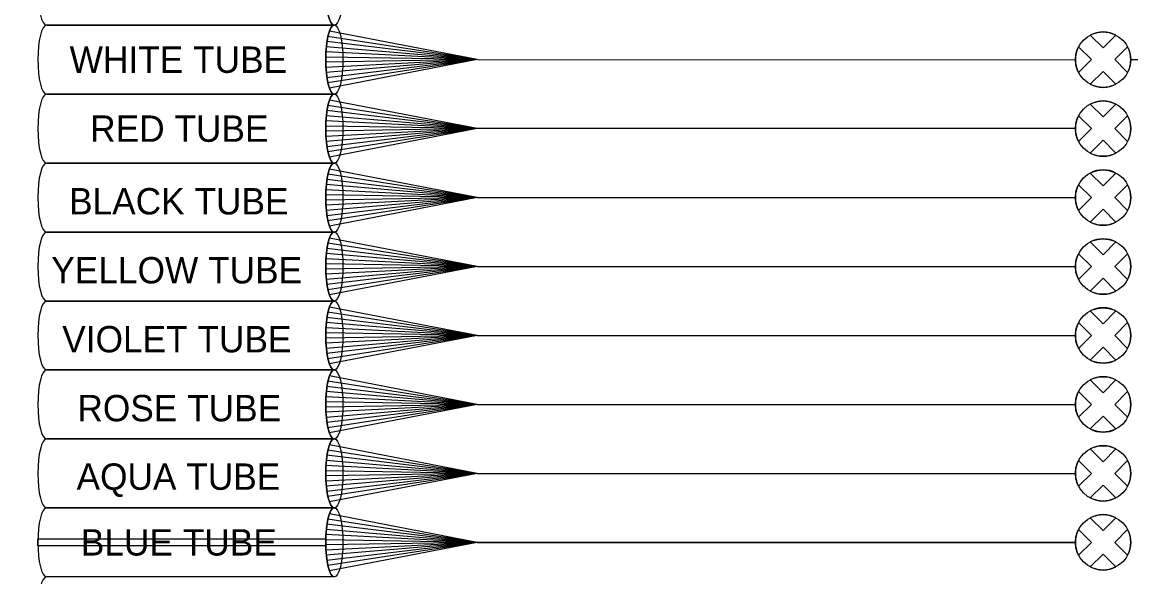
# Model space of a CAD drawing. Extents: x 1805893 to 1833564, y 708898 to 716199.
# Drawn here: x 1831642.7 to 1831739.1, y 715918.7 to 715967 of the extents above; entities that cross this region are included whole.
import ezdxf

# ---------------------------------------------------------------- set-up
doc = ezdxf.new("R2010")
doc.units = 0
doc.layers.add('SH_Data', color=7, linetype='Continuous')

msp = doc.modelspace()

# ---------------------------------------------------------------- linework, layer by layer
at = {"layer": 'SH_Data'}
for p, q in [((1831669.823, 715966.733), (1831644.773, 715966.733)), ((1831644.773, 715966.733), (1831669.823, 715966.733)), ((1831682.244, 715963.733), (1831669.4, 715966.208)), ((1831682.244, 715963.733), (1831669.185, 715965.308)), ((1831682.244, 715963.733), (1831669.27, 715965.758)), ((1831736.727, 715964.75), (1831735.608, 715965.869)), ((1831735.608, 715965.869), (1831736.727, 715964.75)), ((1831736.727, 715964.75), (1831737.846, 715965.869)), ((1831736.727, 715964.75), (1831737.846, 715965.869)), ((1831682.244, 715963.733), (1831669.093, 715964.408)), ((1831682.244, 715963.733), (1831669.128, 715964.858)), ((1831735.71, 715963.733), (1831734.591, 715964.852)), ((1831735.71, 715963.733), (1831734.591, 715964.852)), ((1831737.744, 715963.733), (1831738.863, 715964.852)), ((1831738.863, 715964.852), (1831737.744, 715963.733)), ((1831682.244, 715963.733), (1831669.076, 715963.958)), ((1831682.244, 715963.733), (1831669.076, 715963.508)), ((1831682.244, 715963.733), (1831669.093, 715963.058)), ((1831682.244, 715963.733), (1831669.128, 715962.608)), ((1831682.244, 715963.733), (1831669.185, 715962.158)), ((1831682.244, 715963.733), (1831669.27, 715961.708)), ((1831682.244, 715963.733), (1831669.4, 715961.258)), ((1831682.244, 715963.733), (1831734.316, 715963.711)), ((1831734.591, 715962.614), (1831735.71, 715963.733)), ((1831734.591, 715962.614), (1831735.71, 715963.733)), ((1831738.863, 715962.614), (1831737.744, 715963.733)), ((1831737.744, 715963.733), (1831738.863, 715962.614)), ((1831791.211, 715963.733), (1831739.139, 715963.711)), ((1831735.608, 715961.597), (1831736.727, 715962.716)), ((1831736.727, 715962.716), (1831735.608, 715961.597)), ((1831737.846, 715961.597), (1831736.727, 715962.716)), ((1831737.846, 715961.597), (1831736.727, 715962.716)), ((1831669.823, 715960.733), (1831644.773, 715960.733)), ((1831644.773, 715960.733), (1831669.823, 715960.733)), ((1831682.244, 715957.733), (1831669.27, 715959.758)), ((1831682.244, 715957.733), (1831669.4, 715960.208)), ((1831736.727, 715958.75), (1831735.608, 715959.869)), ((1831735.608, 715959.869), (1831736.727, 715958.75)), ((1831736.727, 715958.75), (1831737.846, 715959.869)), ((1831736.727, 715958.75), (1831737.846, 715959.869)), ((1831682.244, 715957.733), (1831669.128, 715958.858)), ((1831682.244, 715957.733), (1831669.185, 715959.308)), ((1831735.71, 715957.733), (1831734.591, 715958.852)), ((1831735.71, 715957.733), (1831734.591, 715958.852)), ((1831737.744, 715957.733), (1831738.863, 715958.852)), ((1831738.863, 715958.852), (1831737.744, 715957.733)), ((1831682.244, 715957.733), (1831669.076, 715957.958)), ((1831682.244, 715957.733), (1831669.076, 715957.508)), ((1831682.244, 715957.733), (1831669.093, 715958.408)), ((1831682.244, 715957.733), (1831669.093, 715957.058)), ((1831682.244, 715957.733), (1831669.128, 715956.608)), ((1831682.244, 715957.733), (1831669.185, 715956.158)), ((1831682.244, 715957.733), (1831669.27, 715955.708)), ((1831682.244, 715957.733), (1831669.4, 715955.258)), ((1831734.316, 715957.733), (1831682.244, 715957.733)), ((1831734.591, 715956.614), (1831735.71, 715957.733)), ((1831734.591, 715956.614), (1831735.71, 715957.733)), ((1831738.863, 715956.614), (1831737.744, 715957.733)), ((1831737.744, 715957.733), (1831738.863, 715956.614)), ((1831735.608, 715955.597), (1831736.727, 715956.716)), ((1831736.727, 715956.716), (1831735.608, 715955.597)), ((1831737.846, 715955.597), (1831736.727, 715956.716)), ((1831737.846, 715955.597), (1831736.727, 715956.716)), ((1831669.823, 715954.733), (1831644.773, 715954.733)), ((1831644.773, 715954.733), (1831669.823, 715954.733)), ((1831682.244, 715951.733), (1831669.27, 715953.758)), ((1831682.244, 715951.733), (1831669.4, 715954.208)), ((1831736.727, 715952.75), (1831735.608, 715953.869)), ((1831735.608, 715953.869), (1831736.727, 715952.75)), ((1831736.727, 715952.75), (1831737.846, 715953.869)), ((1831736.727, 715952.75), (1831737.846, 715953.869)), ((1831682.244, 715951.733), (1831669.128, 715952.858)), ((1831682.244, 715951.733), (1831669.185, 715953.308)), ((1831735.71, 715951.733), (1831734.591, 715952.852)), ((1831735.71, 715951.733), (1831734.591, 715952.852)), ((1831737.744, 715951.733), (1831738.863, 715952.852)), ((1831738.863, 715952.852), (1831737.744, 715951.733)), ((1831682.244, 715951.733), (1831669.076, 715951.958)), ((1831682.244, 715951.733), (1831669.076, 715951.508)), ((1831682.244, 715951.733), (1831669.093, 715952.408)), ((1831682.244, 715951.733), (1831669.093, 715951.058)), ((1831682.244, 715951.733), (1831669.128, 715950.608)), ((1831682.244, 715951.733), (1831669.185, 715950.158)), ((1831682.244, 715951.733), (1831669.27, 715949.708)), ((1831682.244, 715951.733), (1831669.4, 715949.258)), ((1831682.244, 715951.733), (1831734.316, 715951.733)), ((1831734.591, 715950.614), (1831735.71, 715951.733)), ((1831734.591, 715950.614), (1831735.71, 715951.733)), ((1831738.863, 715950.614), (1831737.744, 715951.733)), ((1831737.744, 715951.733), (1831738.863, 715950.614)), ((1831735.608, 715949.597), (1831736.727, 715950.716)), ((1831736.727, 715950.716), (1831735.608, 715949.597)), ((1831737.846, 715949.597), (1831736.727, 715950.716)), ((1831737.846, 715949.597), (1831736.727, 715950.716)), ((1831644.773, 715948.733), (1831669.823, 715948.733)), ((1831669.823, 715948.733), (1831644.773, 715948.733)), ((1831682.244, 715945.733), (1831669.4, 715948.208)), ((1831736.727, 715946.75), (1831735.608, 715947.869)), ((1831735.608, 715947.869), (1831736.727, 715946.75)), ((1831736.727, 715946.75), (1831737.846, 715947.869)), ((1831736.727, 715946.75), (1831737.846, 715947.869)), ((1831682.244, 715945.733), (1831669.128, 715946.858)), ((1831682.244, 715945.733), (1831669.185, 715947.308)), ((1831682.244, 715945.733), (1831669.27, 715947.758)), ((1831735.71, 715945.733), (1831734.591, 715946.852)), ((1831735.71, 715945.733), (1831734.591, 715946.852)), ((1831737.744, 715945.733), (1831738.863, 715946.852)), ((1831738.863, 715946.852), (1831737.744, 715945.733)), ((1831682.244, 715945.733), (1831669.076, 715945.958)), ((1831682.244, 715945.733), (1831669.093, 715946.408)), ((1831682.244, 715945.733), (1831669.076, 715945.508)), ((1831682.244, 715945.733), (1831669.093, 715945.058)), ((1831682.244, 715945.733), (1831669.128, 715944.608)), ((1831682.244, 715945.733), (1831669.185, 715944.158)), ((1831682.244, 715945.733), (1831669.27, 715943.708)), ((1831682.244, 715945.733), (1831669.4, 715943.258)), ((1831682.244, 715945.733), (1831734.316, 715945.733)), ((1831734.591, 715944.614), (1831735.71, 715945.733)), ((1831734.591, 715944.614), (1831735.71, 715945.733)), ((1831738.863, 715944.614), (1831737.744, 715945.733)), ((1831737.744, 715945.733), (1831738.863, 715944.614)), ((1831735.608, 715943.597), (1831736.727, 715944.716)), ((1831736.727, 715944.716), (1831735.608, 715943.597)), ((1831737.846, 715943.597), (1831736.727, 715944.716)), ((1831737.846, 715943.597), (1831736.727, 715944.716)), ((1831669.823, 715942.733), (1831644.773, 715942.733)), ((1831644.773, 715942.733), (1831669.823, 715942.733)), ((1831644.773, 715942.733), (1831669.823, 715942.733)), ((1831682.244, 715939.733), (1831669.4, 715942.208)), ((1831682.244, 715939.733), (1831669.185, 715941.308)), ((1831682.244, 715939.733), (1831669.27, 715941.758)), ((1831736.727, 715940.75), (1831735.608, 715941.869)), ((1831735.608, 715941.869), (1831736.727, 715940.75)), ((1831736.727, 715940.75), (1831737.846, 715941.869)), ((1831736.727, 715940.75), (1831737.846, 715941.869)), ((1831682.244, 715939.733), (1831669.093, 715940.408)), ((1831682.244, 715939.733), (1831669.128, 715940.858)), ((1831735.71, 715939.733), (1831734.591, 715940.852)), ((1831735.71, 715939.733), (1831734.591, 715940.852)), ((1831737.744, 715939.733), (1831738.863, 715940.852)), ((1831738.863, 715940.852), (1831737.744, 715939.733)), ((1831682.244, 715939.733), (1831669.076, 715939.958)), ((1831682.244, 715939.733), (1831669.076, 715939.508)), ((1831682.244, 715939.733), (1831669.093, 715939.058)), ((1831682.244, 715939.733), (1831669.128, 715938.608)), ((1831682.244, 715939.733), (1831669.185, 715938.158)), ((1831682.244, 715939.733), (1831669.27, 715937.708)), ((1831682.244, 715939.733), (1831669.4, 715937.258)), ((1831682.244, 715939.733), (1831734.316, 715939.733)), ((1831734.591, 715938.614), (1831735.71, 715939.733)), ((1831734.591, 715938.614), (1831735.71, 715939.733)), ((1831738.863, 715938.614), (1831737.744, 715939.733)), ((1831737.744, 715939.733), (1831738.863, 715938.614)), ((1831735.608, 715937.597), (1831736.727, 715938.716)), ((1831736.727, 715938.716), (1831735.608, 715937.597)), ((1831737.846, 715937.597), (1831736.727, 715938.716)), ((1831737.846, 715937.597), (1831736.727, 715938.716)), ((1831669.823, 715936.733), (1831644.773, 715936.733)), ((1831644.773, 715936.733), (1831669.823, 715936.733)), ((1831682.244, 715933.733), (1831669.185, 715935.308)), ((1831682.244, 715933.733), (1831669.27, 715935.758)), ((1831682.244, 715933.733), (1831669.4, 715936.208)), ((1831736.727, 715934.75), (1831735.608, 715935.869)), ((1831735.608, 715935.869), (1831736.727, 715934.75)), ((1831736.727, 715934.75), (1831737.846, 715935.869)), ((1831736.727, 715934.75), (1831737.846, 715935.869)), ((1831682.244, 715933.733), (1831669.093, 715934.408)), ((1831682.244, 715933.733), (1831669.128, 715934.858)), ((1831735.71, 715933.733), (1831734.591, 715934.852)), ((1831735.71, 715933.733), (1831734.591, 715934.852)), ((1831737.744, 715933.733), (1831738.863, 715934.852)), ((1831738.863, 715934.852), (1831737.744, 715933.733)), ((1831682.244, 715933.733), (1831669.076, 715933.958)), ((1831682.244, 715933.733), (1831669.076, 715933.508)), ((1831682.244, 715933.733), (1831669.093, 715933.058)), ((1831682.244, 715933.733), (1831669.128, 715932.608)), ((1831682.244, 715933.733), (1831669.185, 715932.158)), ((1831682.244, 715933.733), (1831669.27, 715931.708)), ((1831682.244, 715933.733), (1831669.4, 715931.258)), ((1831682.244, 715933.733), (1831734.316, 715933.733)), ((1831734.591, 715932.614), (1831735.71, 715933.733)), ((1831734.591, 715932.614), (1831735.71, 715933.733)), ((1831738.863, 715932.614), (1831737.744, 715933.733)), ((1831737.744, 715933.733), (1831738.863, 715932.614)), ((1831735.608, 715931.597), (1831736.727, 715932.716)), ((1831736.727, 715932.716), (1831735.608, 715931.597)), ((1831737.846, 715931.597), (1831736.727, 715932.716)), ((1831737.846, 715931.597), (1831736.727, 715932.716)), ((1831669.823, 715930.733), (1831644.773, 715930.733)), ((1831644.773, 715930.733), (1831669.823, 715930.733)), ((1831682.244, 715927.733), (1831669.27, 715929.758)), ((1831682.244, 715927.733), (1831669.4, 715930.208)), ((1831736.727, 715928.75), (1831735.608, 715929.869)), ((1831735.608, 715929.869), (1831736.727, 715928.75)), ((1831736.727, 715928.75), (1831737.846, 715929.869)), ((1831736.727, 715928.75), (1831737.846, 715929.869)), ((1831682.244, 715927.733), (1831669.128, 715928.858)), ((1831682.244, 715927.733), (1831669.185, 715929.308)), ((1831735.71, 715927.733), (1831734.591, 715928.852)), ((1831735.71, 715927.733), (1831734.591, 715928.852)), ((1831737.744, 715927.733), (1831738.863, 715928.852)), ((1831738.863, 715928.852), (1831737.744, 715927.733)), ((1831682.244, 715927.733), (1831669.076, 715927.958)), ((1831682.244, 715927.733), (1831669.076, 715927.508)), ((1831682.244, 715927.733), (1831669.093, 715928.408)), ((1831682.244, 715927.733), (1831669.093, 715927.058)), ((1831682.244, 715927.733), (1831669.128, 715926.608)), ((1831682.244, 715927.733), (1831669.185, 715926.158)), ((1831682.244, 715927.733), (1831669.27, 715925.708)), ((1831682.244, 715927.733), (1831669.4, 715925.258)), ((1831682.244, 715927.733), (1831734.316, 715927.711)), ((1831734.591, 715926.614), (1831735.71, 715927.733)), ((1831734.591, 715926.614), (1831735.71, 715927.733)), ((1831738.863, 715926.614), (1831737.744, 715927.733)), ((1831737.744, 715927.733), (1831738.863, 715926.614)), ((1831735.608, 715925.597), (1831736.727, 715926.716)), ((1831736.727, 715926.716), (1831735.608, 715925.597)), ((1831737.846, 715925.597), (1831736.727, 715926.716)), ((1831737.846, 715925.597), (1831736.727, 715926.716)), ((1831669.823, 715924.733), (1831644.773, 715924.733)), ((1831644.773, 715924.733), (1831669.823, 715924.733)), ((1831682.244, 715921.733), (1831669.27, 715923.758)), ((1831682.244, 715921.733), (1831669.4, 715924.208)), ((1831736.727, 715922.75), (1831735.608, 715923.869)), ((1831735.608, 715923.869), (1831736.727, 715922.75)), ((1831736.727, 715922.75), (1831737.846, 715923.869)), ((1831736.727, 715922.75), (1831737.846, 715923.869)), ((1831682.244, 715921.733), (1831669.128, 715922.858)), ((1831682.244, 715921.733), (1831669.185, 715923.308)), ((1831735.71, 715921.733), (1831734.591, 715922.852)), ((1831735.71, 715921.733), (1831734.591, 715922.852)), ((1831737.744, 715921.733), (1831738.863, 715922.852)), ((1831738.863, 715922.852), (1831737.744, 715921.733)), ((1831682.244, 715921.733), (1831669.076, 715921.958)), ((1831682.244, 715921.733), (1831669.093, 715922.408)), ((1831682.244, 715921.733), (1831669.076, 715921.508)), ((1831682.244, 715921.733), (1831669.093, 715921.058)), ((1831682.244, 715921.733), (1831669.128, 715920.608)), ((1831682.244, 715921.733), (1831669.185, 715920.158)), ((1831682.244, 715921.733), (1831669.27, 715919.708)), ((1831682.244, 715921.733), (1831669.4, 715919.258)), ((1831682.244, 715921.733), (1831734.316, 715921.733)), ((1831734.316, 715921.733), (1831682.244, 715921.733)), ((1831734.591, 715920.614), (1831735.71, 715921.733)), ((1831734.591, 715920.614), (1831735.71, 715921.733)), ((1831738.863, 715920.614), (1831737.744, 715921.733)), ((1831737.744, 715921.733), (1831738.863, 715920.614)), ((1831735.608, 715919.597), (1831736.727, 715920.716)), ((1831736.727, 715920.716), (1831735.608, 715919.597)), ((1831737.846, 715919.597), (1831736.727, 715920.716)), ((1831737.846, 715919.597), (1831736.727, 715920.716)), ((1831669.823, 715918.733), (1831644.773, 715918.733))]:
    msp.add_line(p, q, dxfattribs=at)
msp.add_lwpolyline([(1831644.027, 715922.033), (1831669.075, 715922.033), (1831669.075, 715921.433), (1831644.027, 715921.433)], close=True, dxfattribs=at)
for centre in [(1831736.727, 715963.733), (1831736.727, 715957.733), (1831736.727, 715951.733), (1831736.727, 715945.733), (1831736.727, 715939.733), (1831736.727, 715933.733), (1831736.727, 715927.733), (1831736.727, 715921.733)]:
    msp.add_circle(centre, 2.411, dxfattribs=at)
for centre, start, end in [((1831736.727, 715963.733), 62.353, 117.647), ((1831736.727, 715963.733), 152.353, 207.647), ((1831736.727, 715963.733), 332.353, 27.647), ((1831736.727, 715963.733), 242.353, 297.647), ((1831736.727, 715957.733), 62.353, 117.647), ((1831736.727, 715957.733), 152.353, 207.647), ((1831736.727, 715957.733), 332.353, 27.647), ((1831736.727, 715957.733), 242.353, 297.647), ((1831736.727, 715951.733), 62.353, 117.647), ((1831736.727, 715951.733), 152.353, 207.647), ((1831736.727, 715951.733), 332.353, 27.647), ((1831736.727, 715951.733), 242.353, 297.647), ((1831736.727, 715945.733), 62.353, 117.647), ((1831736.727, 715945.733), 152.353, 207.647), ((1831736.727, 715945.733), 332.353, 27.647), ((1831736.727, 715945.733), 242.353, 297.647), ((1831736.727, 715939.733), 62.353, 117.647), ((1831736.727, 715939.733), 152.353, 207.647), ((1831736.727, 715939.733), 332.353, 27.647), ((1831736.727, 715939.733), 242.353, 297.647), ((1831736.727, 715933.733), 62.353, 117.647), ((1831736.727, 715933.733), 152.353, 207.647), ((1831736.727, 715933.733), 332.353, 27.647), ((1831736.727, 715933.733), 242.353, 297.647), ((1831736.727, 715927.733), 62.353, 117.647), ((1831736.727, 715927.733), 152.353, 207.647), ((1831736.727, 715927.733), 332.353, 27.647), ((1831736.727, 715927.733), 242.353, 297.647), ((1831736.727, 715921.733), 62.353, 117.647), ((1831736.727, 715921.733), 152.353, 207.647), ((1831736.727, 715921.733), 332.353, 27.647), ((1831736.727, 715921.733), 242.353, 297.647)]:
    msp.add_arc(centre, 2.411, start, end, dxfattribs=at)
for centre, major_axis, ratio, start_param, end_param in [((1831644.17, 715924.733), (0, -86.094), 0.112175, 2.561295, 6.863483), ((1831644.17, 715924.733), (0, -86.094), 0.112175, 2.561295, 6.863483), ((1831644.773, 715969.733), (0, -3), 0.25, 3.141593, 6.283185), ((1831644.773, 715969.733), (0, -3), 0.25, 3.141593, 6.283185), ((1831669.823, 715969.733), (0, -3), 0.25, 3.141593, 6.283185), ((1831644.773, 715963.733), (0, -3), 0.25, 3.141593, 6.283185), ((1831644.773, 715963.733), (0, -3), 0.25, 3.141593, 6.283185), ((1831669.823, 715963.733), (0, -3), 0.25, 3.141593, 6.283185), ((1831644.773, 715957.733), (0, -3), 0.25, 3.141593, 6.283185), ((1831644.773, 715957.733), (0, -3), 0.25, 3.141593, 6.283185), ((1831669.823, 715957.733), (0, -3), 0.25, 3.141593, 6.283185), ((1831644.773, 715951.733), (0, -3), 0.25, 3.141593, 6.283185), ((1831644.773, 715951.733), (0, -3), 0.25, 3.141593, 6.283185), ((1831669.823, 715951.733), (0, -3), 0.25, 3.141593, 6.283185), ((1831644.773, 715945.733), (0, -3), 0.25, 3.141593, 6.283185), ((1831644.773, 715945.733), (0, -3), 0.25, 3.141593, 6.283185), ((1831669.823, 715945.733), (0, -3), 0.25, 3.141593, 6.283185), ((1831644.773, 715939.733), (0, -3), 0.25, 3.141593, 6.283185), ((1831644.773, 715939.733), (0, -3), 0.25, 3.141593, 6.283185), ((1831669.823, 715939.733), (0, -3), 0.25, 3.141593, 6.283185), ((1831644.773, 715933.733), (0, -3), 0.25, 3.141593, 6.283185), ((1831644.773, 715933.733), (0, -3), 0.25, 3.141593, 6.283185), ((1831669.823, 715933.733), (0, -3), 0.25, 3.141593, 6.283185), ((1831644.773, 715927.733), (0, -3), 0.25, 3.141593, 6.283185), ((1831644.773, 715927.733), (0, -3), 0.25, 3.141593, 6.283185), ((1831669.823, 715927.733), (0, -3), 0.25, 3.141593, 6.283185), ((1831644.773, 715921.733), (0, -3), 0.25, 3.141593, 6.283185), ((1831644.773, 715921.733), (0, -3), 0.25, 3.141593, 6.283185), ((1831669.823, 715921.733), (0, -3), 0.25, 3.141593, 6.283185), ((1831644.773, 715915.733), (0, -3), 0.25, 3.141593, 6.283185)]:
    msp.add_ellipse(centre, major_axis=major_axis, ratio=ratio, start_param=start_param, end_param=end_param, dxfattribs=at)
for centre in [(1831669.823, 715969.733), (1831669.823, 715963.733), (1831669.823, 715957.733), (1831669.823, 715951.733), (1831669.823, 715945.733), (1831669.823, 715939.733), (1831669.823, 715933.733), (1831669.823, 715927.733), (1831669.823, 715921.733)]:
    msp.add_ellipse(centre, major_axis=(0, -3), ratio=0.25, dxfattribs=at)

# ---------------------------------------------------------------- texts
for s, height, p in [('WHITE TUBE', 2.2947, (1831646.792, 715962.585)), ('RED TUBE', 2.2947, (1831648.58, 715956.585)), ('BLACK TUBE', 2.2947, (1831646.738, 715950.264)), ('YELLOW TUBE', 2.29468, (1831645.194, 715944.264)), ('VIOLET TUBE', 2.29468, (1831646.144, 715938.264)), ('ROSE TUBE', 2.2947, (1831647.467, 715932.264)), ('AQUA TUBE', 2.2947, (1831647.391, 715926.304)), ('BLUE TUBE', 2.2947, (1831647.768, 715920.585))]:
    msp.add_text(s, height=height, dxfattribs=at).set_placement(p)

doc.saveas('drawing.dxf')
